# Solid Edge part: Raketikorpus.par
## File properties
Author: Egon 815
Template: Normal.par
Last saved by: Egon 815
Revision: 5
Application: Solid Edge
Accuracy: 0,990
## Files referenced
..\Laev.asm
.C:\Kool\3D Modelleerimine\LaevaJoonis\Laev.asm
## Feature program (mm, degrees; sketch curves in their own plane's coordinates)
sketch for "unnamed Protrusion 1" plane through (0, 0, 15705.2991) normal (0, 0, 1) x-axis (1, 0, 0)
  line (5837.8486, 30614.9825) -> (5837.8486, 6999.665)
  line (5837.8486, 6999.665) -> (-5878.6313, 6999.665)
  line (-5878.6313, 6999.665) -> (-5878.6313, 30614.9825)
  line (-5878.6313, 30614.9825) -> (5837.8486, 30614.9825)
extrude "unnamed Protrusion 1" add finite 15369.9695 along -normal
sketch for "unnamed Cutout 1" #1 plane through (0, 0, 15705.2991) normal (0, 0, 1) x-axis (1, 0, 0)
  line (0, 0) -> (0, 0)
  line (-5129.348, 9677.0977) -> (-3129.3493, 9677.0977)
  line (-3129.3493, 9677.0977) -> (-3129.3494, 7677.0977)
  line (-5129.348, 7677.0977) -> (-3129.3494, 7677.0977)
  line (-5129.348, 7677.0977) -> (-5129.348, 9677.0977)
sketch for "unnamed Cutout 1" #2 plane through (0, 0, 15705.2991) normal (0, 0, 1) x-axis (1, 0, 0)
  line (-2348.7607, 7677.0977) -> (-2348.7607, 9677.0977)
  line (-2348.7607, 9677.0977) -> (-348.7603, 9677.0977)
  line (-348.7603, 9677.0977) -> (-348.761, 7677.0977)
  line (-2348.7607, 7677.0977) -> (-348.761, 7677.0977)
sketch for "unnamed Cutout 1" #3 plane through (0, 0, 15705.2991) normal (0, 0, 1) x-axis (1, 0, 0)
  line (431.8267, 9677.0977) -> (2431.8267, 9677.0977)
  line (2431.8267, 9677.0977) -> (2431.8267, 7677.0977)
  line (431.8267, 7677.0977) -> (2431.8267, 7677.0977)
  line (431.8267, 7677.0977) -> (431.8267, 9677.0977)
sketch for "unnamed Cutout 1" #4 plane through (0, 0, 15705.2991) normal (0, 0, 1) x-axis (1, 0, 0)
  line (3212.414, 9677.0977) -> (5212.414, 9677.0977)
  line (5212.414, 9677.0977) -> (5212.414, 7677.0977)
  line (3212.414, 7677.0977) -> (5212.414, 7677.0977)
  line (3212.414, 7677.0977) -> (3212.414, 9677.0977)
sketch for "unnamed Cutout 1" #5 plane through (0, 0, 15705.2991) normal (0, 0, 1) x-axis (1, 0, 0)
  line (5212.414, 11715.5605) -> (3212.414, 11715.5909)
  line (3212.414, 11715.5909) -> (3212.414, 13715.5757)
  line (5212.414, 13715.5757) -> (3212.414, 13715.5757)
  line (5212.414, 13715.5757) -> (5212.414, 11715.5605)
sketch for "unnamed Cutout 1" #6 plane through (0, 0, 15705.2991) normal (0, 0, 1) x-axis (1, 0, 0)
  line (2431.8267, 11715.6028) -> (431.8267, 11715.6332)
  line (431.8267, 11715.6332) -> (431.8267, 13715.5757)
  line (2431.8267, 13715.5757) -> (431.8267, 13715.5757)
  line (2431.8267, 13715.5757) -> (2431.8267, 11715.6028)
sketch for "unnamed Cutout 1" #7 plane through (0, 0, 15705.2991) normal (0, 0, 1) x-axis (1, 0, 0)
  line (-348.7595, 11715.645) -> (-2348.7607, 11715.6755)
  line (-2348.7607, 11715.6755) -> (-2348.7607, 13715.5757)
  line (-348.7588, 13715.5757) -> (-2348.7607, 13715.5757)
  line (-348.7588, 13715.5757) -> (-348.7595, 11715.645)
sketch for "unnamed Cutout 1" #8 plane through (0, 0, 15705.2991) normal (0, 0, 1) x-axis (1, 0, 0)
  line (-3129.349, 13715.5757) -> (-3129.3491, 11715.6873)
  line (-3129.3491, 11715.6873) -> (-5129.348, 11715.7177)
  line (-5129.348, 11715.7177) -> (-5129.348, 13715.5757)
  line (-3129.349, 13715.5757) -> (-5129.348, 13715.5757)
sketch for "unnamed Cutout 1" #9 plane through (0, 0, 15705.2991) normal (0, 0, 1) x-axis (1, 0, 0)
  line (-3129.3489, 15754.0536) -> (-5129.348, 15754.0536)
  line (-5129.348, 15754.0536) -> (-5129.348, 17754.0536)
  line (-5129.348, 17754.0536) -> (-3129.3487, 17754.0536)
  line (-3129.3487, 17754.0536) -> (-3129.3489, 15754.0536)
sketch for "unnamed Cutout 1" #10 plane through (0, 0, 15705.2991) normal (0, 0, 1) x-axis (1, 0, 0)
  line (-348.7573, 17754.0536) -> (-348.758, 15754.0536)
  line (-348.758, 15754.0536) -> (-2348.7607, 15754.0536)
  line (-2348.7607, 15754.0536) -> (-2348.7607, 17754.0536)
  line (-2348.7607, 17754.0536) -> (-348.7573, 17754.0536)
sketch for "unnamed Cutout 1" #11 plane through (0, 0, 15705.2991) normal (0, 0, 1) x-axis (1, 0, 0)
  line (2431.8267, 15754.0536) -> (431.8267, 15754.0536)
  line (431.8267, 15754.0536) -> (431.8267, 17754.0536)
  line (431.8267, 17754.0536) -> (2431.8267, 17754.0536)
  line (2431.8267, 17754.0536) -> (2431.8267, 15754.0536)
sketch for "unnamed Cutout 1" #12 plane through (0, 0, 15705.2991) normal (0, 0, 1) x-axis (1, 0, 0)
  line (5212.414, 15754.0536) -> (3212.414, 15754.0536)
  line (3212.414, 15754.0536) -> (3212.414, 17754.0536)
  line (3212.414, 17754.0536) -> (5212.414, 17754.0536)
  line (5212.414, 17754.0536) -> (5212.414, 15754.0536)
sketch for "unnamed Cutout 1" #13 plane through (0, 0, 15705.2991) normal (0, 0, 1) x-axis (1, 0, 0)
  line (5212.414, 19792.5316) -> (3212.414, 19792.5316)
  line (3212.414, 19792.5316) -> (3212.414, 21846.9875)
  line (5212.414, 21861.8146) -> (3212.414, 21846.9875)
  line (5212.414, 21861.8146) -> (5212.414, 19792.5316)
sketch for "unnamed Cutout 1" #14 plane through (0, 0, 15705.2991) normal (0, 0, 1) x-axis (1, 0, 0)
  line (2431.8267, 19792.5316) -> (431.8267, 19792.5316)
  line (431.8267, 19792.5316) -> (431.8267, 21826.3735)
  line (2431.8267, 21841.2006) -> (431.8267, 21826.3735)
  line (2431.8267, 21841.2006) -> (2431.8267, 19792.5316)
sketch for "unnamed Cutout 1" #15 plane through (0, 0, 15705.2991) normal (0, 0, 1) x-axis (1, 0, 0)
  line (-348.7565, 19792.5316) -> (-2348.7607, 19792.5316)
  line (-2348.7607, 19792.5316) -> (-2348.7607, 21805.7595)
  line (-348.7557, 21820.5866) -> (-2348.7607, 21805.7595)
  line (-348.7557, 21820.5866) -> (-348.7565, 19792.5316)
sketch for "unnamed Cutout 1" #16 plane through (0, 0, 15705.2991) normal (0, 0, 1) x-axis (1, 0, 0)
  line (-3129.3486, 19792.5316) -> (-5129.348, 19792.5316)
  line (-5129.348, 19792.5316) -> (-5129.348, 21785.1455)
  line (-3129.3485, 21799.9726) -> (-5129.348, 21785.1455)
  line (-3129.3485, 21799.9726) -> (-3129.3486, 19792.5316)
sketch for "unnamed Cutout 1" #17 plane through (0, 0, 15705.2991) normal (0, 0, 1) x-axis (1, 0, 0)
  line (-3129.3483, 23831.0095) -> (-5129.348, 23831.0095)
  line (-5129.348, 23831.0095) -> (-5129.348, 25831.0095)
  line (-5129.348, 25831.0095) -> (-3129.3482, 25831.0095)
  line (-3129.3482, 25831.0095) -> (-3129.3483, 23831.0095)
sketch for "unnamed Cutout 1" #18 plane through (0, 0, 15705.2991) normal (0, 0, 1) x-axis (1, 0, 0)
  line (-348.7542, 25831.0095) -> (-348.755, 23831.0095)
  line (-348.755, 23831.0095) -> (-2348.7607, 23831.0095)
  line (-2348.7607, 23831.0095) -> (-2348.7607, 25831.0095)
  line (-2348.7607, 25831.0095) -> (-348.7542, 25831.0095)
sketch for "unnamed Cutout 1" #19 plane through (0, 0, 15705.2991) normal (0, 0, 1) x-axis (1, 0, 0)
  line (5212.414, 23831.0095) -> (3212.414, 23831.0095)
  line (3212.414, 23831.0095) -> (3212.414, 25831.0095)
  line (3212.414, 25831.0095) -> (5212.414, 25831.0095)
  line (5212.414, 25831.0095) -> (5212.414, 23831.0095)
sketch for "unnamed Cutout 1" #20 plane through (0, 0, 15705.2991) normal (0, 0, 1) x-axis (1, 0, 0)
  line (5212.414, 27869.4874) -> (3212.414, 27869.4874)
  line (3212.414, 27869.4874) -> (3212.414, 29869.4874)
  line (5212.414, 29869.4874) -> (3212.414, 29869.4874)
  line (5212.414, 29869.4874) -> (5212.414, 27869.4874)
sketch for "unnamed Cutout 1" #21 plane through (0, 0, 15705.2991) normal (0, 0, 1) x-axis (1, 0, 0)
  line (2431.8267, 27869.4874) -> (431.8267, 27869.4874)
  line (431.8267, 27869.4874) -> (431.8267, 29869.4874)
  line (2431.8267, 29869.4874) -> (431.8267, 29869.4874)
  line (2431.8267, 29869.4874) -> (2431.8267, 27869.4874)
sketch for "unnamed Cutout 1" #22 plane through (0, 0, 15705.2991) normal (0, 0, 1) x-axis (1, 0, 0)
  line (-348.7535, 27869.4874) -> (-2348.7607, 27869.4874)
  line (-2348.7607, 27869.4874) -> (-2348.7607, 29869.4874)
  line (-348.7527, 29869.4874) -> (-2348.7607, 29869.4874)
  line (-348.7527, 29869.4874) -> (-348.7535, 27869.4874)
sketch for "unnamed Cutout 1" #23 plane through (0, 0, 15705.2991) normal (0, 0, 1) x-axis (1, 0, 0)
  line (-3129.3481, 27869.4874) -> (-5129.348, 27869.4874)
  line (-5129.348, 27869.4874) -> (-5129.348, 29869.4874)
  line (-3129.3479, 29869.4874) -> (-5129.348, 29869.4874)
  line (-3129.3479, 29869.4874) -> (-3129.3481, 27869.4874)
sketch for "unnamed Cutout 1" #24 plane through (0, 0, 15705.2991) normal (0, 0, 1) x-axis (1, 0, 0)
  line (2431.8267, 23831.0095) -> (431.8267, 23831.0095)
  line (431.8267, 23831.0095) -> (431.8267, 25831.0095)
  line (431.8267, 25831.0095) -> (2431.8267, 25831.0095)
  line (2431.8267, 25831.0095) -> (2431.8267, 23831.0095)
extrude "unnamed Cutout 1" cut to key point along -normal
chamfer "Chamfer_1" setback 350
sketch for "ExtrudedProtrusion_2" #1 plane through (0, 0, 0) normal (0, 0, 1) x-axis (1, 0, 0)
  line (0, 0) -> (0, 0)
  line (10144.4558, 14192.1581) -> (5837.8486, 14192.1581)
  line (5837.8486, 14192.1581) -> (5837.8486, 8643.7236)
  line (5837.8486, 8643.7236) -> (10144.4558, 8643.7236)
  line (10144.4558, 8643.7236) -> (10144.4558, 14192.1581)
sketch for "ExtrudedProtrusion_2" #2 plane through (0, 0, 0) normal (0, 0, 1) x-axis (1, 0, 0)
  line (-8169.2584, 9380.9282) -> (-8169.2584, 21525.4039)
  line (-8169.2584, 21525.4039) -> (-5878.6313, 21525.4039)
  line (-5878.6313, 21525.4039) -> (-5878.6313, 9380.9282)
  line (-5878.6313, 9380.9282) -> (-8169.2584, 9380.9282)
sketch for "ExtrudedProtrusion_2" #3 plane through (0, 0, 0) normal (0, 0, 1) x-axis (1, 0, 0)
  line (-1767.2185, 30614.9825) -> (-1767.2185, 32467.0721)
  line (-1767.2185, 32467.0721) -> (-5065.2391, 32467.0721)
  line (-5065.2391, 32467.0721) -> (-5065.2391, 30614.9825)
  line (-5065.2391, 30614.9825) -> (-1767.2185, 30614.9825)
extrude "ExtrudedProtrusion_2" add finite 11540.2929 along +normal
chamfer "Chamfer_2" setback 1000
chamfer "Chamfer_5" setback 200
sketch for "unnamed Protrusion 2" plane through (0, 0, 0) normal (0, 0, 1) x-axis (1, 0, 0)
  line (-11685.2712, 23908.2437) -> (-11685.2712, 21661.7276)
  line (-11685.2712, 21661.7276) -> (-10187.5938, 21661.7276)
  line (-10187.5938, 21661.7276) -> (-10187.5938, 23908.2437)
  line (-10187.5938, 23908.2437) -> (-11685.2712, 23908.2437)
extrude "unnamed Protrusion 2" add to key point along +normal
draft "Draft_11"  Angles1 = 29 deg
sketch for "ExtrudedProtrusion_4" plane through (-10936.4325, 22784.9857, 0) normal (0, 0, -1) x-axis (1, 0, 0)
  line (-748.8387, -8662.7501) -> (-748.8387, 17104.27)
  line (-748.8387, 17104.27) -> (18261.0456, 17104.27)
  line (18261.0456, 17104.27) -> (18261.0456, -8662.7501)
  line (18261.0456, -8662.7501) -> (-748.8387, -8662.7501)
extrude "ExtrudedProtrusion_4" add finite 8610.8356 symmetric
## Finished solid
Body 1: solid body, 174 faces, 426 edges, 278 vertices.
  Faces by surface: plane 174
  Edges by curve: line 426
Bounding box of the edges (mm): 21829.727 x 26786.356 x 20010.717, from (-11685.2712, 5680.7156, -4305.4178) to (10144.4558, 32467.0721, 15705.2991).
Planar faces by outward normal: +x 29, +y 30, +z 31, -x 28, -y 25, -z 3, oblique 28
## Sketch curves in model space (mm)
line (-11685.2712, 5680.7156, 0) -> (7324.6131, 5680.7156, 0)
line (7324.6131, 5680.7156, 0) -> (7324.6131, 31447.7358, 0)
line (7324.6131, 31447.7358, 0) -> (-11685.2712, 31447.7358, 0)
line (-11685.2712, 31447.7358, 0) -> (-11685.2712, 5680.7156, 0)
line (10144.4558, 8643.7236, 0) -> (10144.4558, 14192.1581, 0)
line (10144.4558, 14192.1581, 0) -> (5837.8486, 14192.1581, 0)
line (5837.8486, 14192.1581, 0) -> (5837.8486, 8643.7236, 0)
line (5837.8486, 8643.7236, 0) -> (10144.4558, 8643.7236, 0)
line (-5878.6313, 9380.9282, 0) -> (-8169.2584, 9380.9282, 0)
line (-8169.2584, 9380.9282, 0) -> (-8169.2584, 21525.4039, 0)
line (-8169.2584, 21525.4039, 0) -> (-5878.6313, 21525.4039, 0)
line (-5878.6313, 21525.4039, 0) -> (-5878.6313, 9380.9282, 0)
line (-1767.2185, 30614.9825, 0) -> (-1767.2185, 32467.0721, 0)
line (-1767.2185, 32467.0721, 0) -> (-5065.2391, 32467.0721, 0)
line (-5065.2391, 32467.0721, 0) -> (-5065.2391, 30614.9825, 0)
line (-5065.2391, 30614.9825, 0) -> (-1767.2185, 30614.9825, 0)
line (-10187.5938, 21661.7276, 0) -> (-10187.5938, 23908.2437, 0)
line (-10187.5938, 23908.2437, 0) -> (-11685.2712, 23908.2437, 0)
line (-11685.2712, 23908.2437, 0) -> (-11685.2712, 21661.7276, 0)
line (-11685.2712, 21661.7276, 0) -> (-10187.5938, 21661.7276, 0)
line (3212.414, 11715.5909, 15705.2991) -> (3212.414, 13715.5757, 15705.2991)
line (5212.414, 13715.5757, 15705.2991) -> (3212.414, 13715.5757, 15705.2991)
line (5212.414, 13715.5757, 15705.2991) -> (5212.414, 11715.5605, 15705.2991)
line (5212.414, 11715.5605, 15705.2991) -> (3212.414, 11715.5909, 15705.2991)
line (-2348.7607, 15754.0536, 15705.2991) -> (-2348.7607, 17754.0536, 15705.2991)
line (-2348.7607, 17754.0536, 15705.2991) -> (-348.7573, 17754.0536, 15705.2991)
line (-348.7573, 17754.0536, 15705.2991) -> (-348.758, 15754.0536, 15705.2991)
line (-348.758, 15754.0536, 15705.2991) -> (-2348.7607, 15754.0536, 15705.2991)
line (3212.414, 19792.5316, 15705.2991) -> (3212.414, 21846.9875, 15705.2991)
line (5212.414, 21861.8146, 15705.2991) -> (3212.414, 21846.9875, 15705.2991)
line (5212.414, 21861.8146, 15705.2991) -> (5212.414, 19792.5316, 15705.2991)
line (5212.414, 19792.5316, 15705.2991) -> (3212.414, 19792.5316, 15705.2991)
line (-2348.7607, 23831.0095, 15705.2991) -> (-2348.7607, 25831.0095, 15705.2991)
line (-2348.7607, 25831.0095, 15705.2991) -> (-348.7542, 25831.0095, 15705.2991)
line (-348.7542, 25831.0095, 15705.2991) -> (-348.755, 23831.0095, 15705.2991)
line (-348.755, 23831.0095, 15705.2991) -> (-2348.7607, 23831.0095, 15705.2991)
line (-2348.7607, 27869.4874, 15705.2991) -> (-2348.7607, 29869.4874, 15705.2991)
line (-348.7527, 29869.4874, 15705.2991) -> (-2348.7607, 29869.4874, 15705.2991)
line (-348.7527, 29869.4874, 15705.2991) -> (-348.7535, 27869.4874, 15705.2991)
line (-348.7535, 27869.4874, 15705.2991) -> (-2348.7607, 27869.4874, 15705.2991)
line (3212.414, 27869.4874, 15705.2991) -> (3212.414, 29869.4874, 15705.2991)
line (5212.414, 27869.4874, 15705.2991) -> (3212.414, 27869.4874, 15705.2991)
line (5212.414, 29869.4874, 15705.2991) -> (5212.414, 27869.4874, 15705.2991)
line (5212.414, 29869.4874, 15705.2991) -> (3212.414, 29869.4874, 15705.2991)
line (-3129.3481, 27869.4874, 15705.2991) -> (-5129.348, 27869.4874, 15705.2991)
line (-5129.348, 27869.4874, 15705.2991) -> (-5129.348, 29869.4874, 15705.2991)
line (-3129.3479, 29869.4874, 15705.2991) -> (-5129.348, 29869.4874, 15705.2991)
line (-3129.3479, 29869.4874, 15705.2991) -> (-3129.3481, 27869.4874, 15705.2991)
line (2431.8267, 29869.4874, 15705.2991) -> (431.8267, 29869.4874, 15705.2991)
line (2431.8267, 29869.4874, 15705.2991) -> (2431.8267, 27869.4874, 15705.2991)
line (2431.8267, 27869.4874, 15705.2991) -> (431.8267, 27869.4874, 15705.2991)
line (431.8267, 27869.4874, 15705.2991) -> (431.8267, 29869.4874, 15705.2991)
line (5212.414, 9677.0977, 15705.2991) -> (5212.414, 7677.0977, 15705.2991)
line (3212.414, 9677.0977, 15705.2991) -> (5212.414, 9677.0977, 15705.2991)
line (3212.414, 7677.0977, 15705.2991) -> (3212.414, 9677.0977, 15705.2991)
line (3212.414, 7677.0977, 15705.2991) -> (5212.414, 7677.0977, 15705.2991)
line (5837.8486, 30614.9825, 15705.2991) -> (5837.8486, 6999.665, 15705.2991)
line (5837.8486, 6999.665, 15705.2991) -> (-5878.6313, 6999.665, 15705.2991)
line (-5878.6313, 6999.665, 15705.2991) -> (-5878.6313, 30614.9825, 15705.2991)
line (-5878.6313, 30614.9825, 15705.2991) -> (5837.8486, 30614.9825, 15705.2991)
line (-3129.3493, 9677.0977, 15705.2991) -> (-3129.3494, 7677.0977, 15705.2991)
line (-5129.348, 9677.0977, 15705.2991) -> (-3129.3493, 9677.0977, 15705.2991)
line (-5129.348, 7677.0977, 15705.2991) -> (-5129.348, 9677.0977, 15705.2991)
line (-5129.348, 7677.0977, 15705.2991) -> (-3129.3494, 7677.0977, 15705.2991)
line (-348.7603, 9677.0977, 15705.2991) -> (-348.761, 7677.0977, 15705.2991)
line (-2348.7607, 9677.0977, 15705.2991) -> (-348.7603, 9677.0977, 15705.2991)
line (-2348.7607, 7677.0977, 15705.2991) -> (-2348.7607, 9677.0977, 15705.2991)
line (-2348.7607, 7677.0977, 15705.2991) -> (-348.761, 7677.0977, 15705.2991)
line (2431.8267, 9677.0977, 15705.2991) -> (2431.8267, 7677.0977, 15705.2991)
line (431.8267, 9677.0977, 15705.2991) -> (2431.8267, 9677.0977, 15705.2991)
line (431.8267, 7677.0977, 15705.2991) -> (431.8267, 9677.0977, 15705.2991)
line (431.8267, 7677.0977, 15705.2991) -> (2431.8267, 7677.0977, 15705.2991)
line (-2348.7607, 19792.5316, 15705.2991) -> (-2348.7607, 21805.7595, 15705.2991)
line (-348.7565, 19792.5316, 15705.2991) -> (-2348.7607, 19792.5316, 15705.2991)
line (-348.7557, 21820.5866, 15705.2991) -> (-348.7565, 19792.5316, 15705.2991)
line (-348.7557, 21820.5866, 15705.2991) -> (-2348.7607, 21805.7595, 15705.2991)
line (5212.414, 17754.0536, 15705.2991) -> (5212.414, 15754.0536, 15705.2991)
line (5212.414, 15754.0536, 15705.2991) -> (3212.414, 15754.0536, 15705.2991)
line (3212.414, 15754.0536, 15705.2991) -> (3212.414, 17754.0536, 15705.2991)
line (3212.414, 17754.0536, 15705.2991) -> (5212.414, 17754.0536, 15705.2991)
line (-2348.7607, 11715.6755, 15705.2991) -> (-2348.7607, 13715.5757, 15705.2991)
line (-348.7595, 11715.645, 15705.2991) -> (-2348.7607, 11715.6755, 15705.2991)
line (-348.7588, 13715.5757, 15705.2991) -> (-348.7595, 11715.645, 15705.2991)
line (-348.7588, 13715.5757, 15705.2991) -> (-2348.7607, 13715.5757, 15705.2991)
line (-5129.348, 11715.7177, 15705.2991) -> (-5129.348, 13715.5757, 15705.2991)
line (-3129.349, 13715.5757, 15705.2991) -> (-5129.348, 13715.5757, 15705.2991)
line (-3129.349, 13715.5757, 15705.2991) -> (-3129.3491, 11715.6873, 15705.2991)
line (-3129.3491, 11715.6873, 15705.2991) -> (-5129.348, 11715.7177, 15705.2991)
line (431.8267, 11715.6332, 15705.2991) -> (431.8267, 13715.5757, 15705.2991)
line (2431.8267, 13715.5757, 15705.2991) -> (431.8267, 13715.5757, 15705.2991)
line (2431.8267, 13715.5757, 15705.2991) -> (2431.8267, 11715.6028, 15705.2991)
line (2431.8267, 11715.6028, 15705.2991) -> (431.8267, 11715.6332, 15705.2991)
line (431.8267, 15754.0536, 15705.2991) -> (431.8267, 17754.0536, 15705.2991)
line (431.8267, 17754.0536, 15705.2991) -> (2431.8267, 17754.0536, 15705.2991)
line (2431.8267, 17754.0536, 15705.2991) -> (2431.8267, 15754.0536, 15705.2991)
line (2431.8267, 15754.0536, 15705.2991) -> (431.8267, 15754.0536, 15705.2991)
line (-5129.348, 15754.0536, 15705.2991) -> (-5129.348, 17754.0536, 15705.2991)
line (-5129.348, 17754.0536, 15705.2991) -> (-3129.3487, 17754.0536, 15705.2991)
line (-3129.3487, 17754.0536, 15705.2991) -> (-3129.3489, 15754.0536, 15705.2991)
line (-3129.3489, 15754.0536, 15705.2991) -> (-5129.348, 15754.0536, 15705.2991)
line (-5129.348, 19792.5316, 15705.2991) -> (-5129.348, 21785.1455, 15705.2991)
line (-3129.3485, 21799.9726, 15705.2991) -> (-5129.348, 21785.1455, 15705.2991)
line (-3129.3485, 21799.9726, 15705.2991) -> (-3129.3486, 19792.5316, 15705.2991)
line (-3129.3486, 19792.5316, 15705.2991) -> (-5129.348, 19792.5316, 15705.2991)
line (431.8267, 19792.5316, 15705.2991) -> (431.8267, 21826.3735, 15705.2991)
line (2431.8267, 21841.2006, 15705.2991) -> (431.8267, 21826.3735, 15705.2991)
line (2431.8267, 21841.2006, 15705.2991) -> (2431.8267, 19792.5316, 15705.2991)
line (2431.8267, 19792.5316, 15705.2991) -> (431.8267, 19792.5316, 15705.2991)
line (3212.414, 23831.0095, 15705.2991) -> (3212.414, 25831.0095, 15705.2991)
line (3212.414, 25831.0095, 15705.2991) -> (5212.414, 25831.0095, 15705.2991)
line (5212.414, 25831.0095, 15705.2991) -> (5212.414, 23831.0095, 15705.2991)
line (5212.414, 23831.0095, 15705.2991) -> (3212.414, 23831.0095, 15705.2991)
line (-5129.348, 23831.0095, 15705.2991) -> (-5129.348, 25831.0095, 15705.2991)
line (-5129.348, 25831.0095, 15705.2991) -> (-3129.3482, 25831.0095, 15705.2991)
line (-3129.3482, 25831.0095, 15705.2991) -> (-3129.3483, 23831.0095, 15705.2991)
line (-3129.3483, 23831.0095, 15705.2991) -> (-5129.348, 23831.0095, 15705.2991)
line (431.8267, 23831.0095, 15705.2991) -> (431.8267, 25831.0095, 15705.2991)
line (431.8267, 25831.0095, 15705.2991) -> (2431.8267, 25831.0095, 15705.2991)
line (2431.8267, 25831.0095, 15705.2991) -> (2431.8267, 23831.0095, 15705.2991)
line (2431.8267, 23831.0095, 15705.2991) -> (431.8267, 23831.0095, 15705.2991)
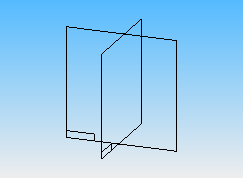
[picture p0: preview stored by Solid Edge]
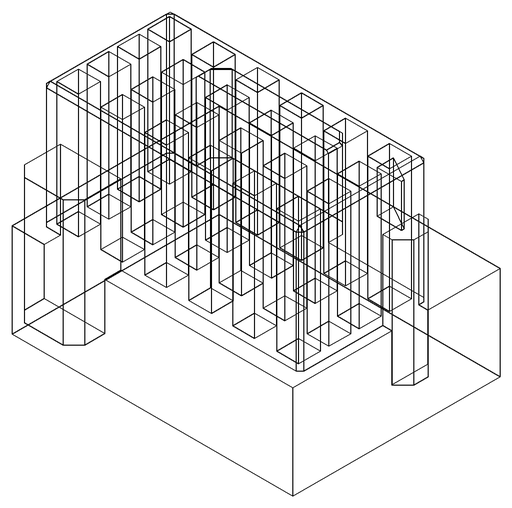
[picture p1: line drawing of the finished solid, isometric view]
